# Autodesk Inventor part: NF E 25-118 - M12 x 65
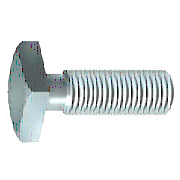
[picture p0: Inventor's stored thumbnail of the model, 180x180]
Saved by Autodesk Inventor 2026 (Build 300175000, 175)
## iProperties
Created: 2025-01
Part Number: NF E 25-118 - M12 x 65
Material: Acier, doux
Description: Vis à tête carrée. Produit de classe C. Symbole Q
Document SubType Name: Modeling
Standard: NF E 25-118
Designer: thierry.jost
Standards Organization: AFNOR
Language: fr-FR
Size Designation: M12 x 65
Categories: <MemberInstance><Categories><Category DisplayName="Visserie" InternalName="e4da775c-781d-43d5-af7c-5136215cf5a6" Mnemonic="FSTN"><Category DisplayName="Vis" Int
Density: 7.85 g/cm^3
Appearance: Semi-poli
IsCustomPart: 0
Author: thierry.jost
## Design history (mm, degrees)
revolve "Corps" stored, may be unused: angle "d5" = 90 deg
sketch "Esquisse2"
  geometry: L1 (-17.819, 0)-(17.819, 0) reference; L2 (0, -17.819)-(0, 17.819) reference; L3 (0, 12.728)-(12.728, 0); L4 (12.728, 0)-(0, -12.728); L5 (0, -12.728)-(-12.728, 0); L6 (-12.728, 0)-(0, 12.728); 1 further point
  constraints: 8 end point, 2 midpoint, 1 point on line, 7 other
  dimensions: "d6" = 18 distance between parallel lines of L3 L5 (= SW)
extrude "Tête" join sketch "Esquisse2" distance "d7" = 7.5 (= KOH); taper "d8" = 0 deg
revolve "Congé1" stored, may be unused: angle "d11" = 90 deg
workaxis "Work Axis1"
workplane "Work Plane1"
body "Solid1"
feature "Filetage" dims "d12" = 30 (= GEL), "d13" = 0
chamfer "Chanfrein1" distance "d14" = 0.94722 (= -0.5 x SPD + 0.5 x NND); stored, may be unused: second distance "d15" = 1.07364 (computed from GUL), angle "d19" = 45 deg
sketch "Esquisse1"
  geometry: L1 (-13, 0)-(78, 0) reference; L2 (0, -1.2)-(0, 7.2) reference; L3 (0, 0)-(65, 0); L4 (65, 0)-(65, 6); L5 (65, 6)-(35, 6); L6 (35, 6)-(33.926, 6); L7 (33.926, 6)-(0, 6); L8 (0, 6)-(0, 0)
  constraints: 12 end point, 3 parallel, 2 collinear, 2 perpendicular
  dimensions: "d0" = 12 diameter of L7 L3 (= BDM); "d1" = 12 diameter of L5 L3 (= NND); "d2" = 65 distance between parallel lines of L4 L8 (= NLG); "d3" = 30 distance from line of L5.end L4 (= GEL); "d4" = 1.07354 distance of L5.end L6.end (= GAL)
sketch "Esquisse3"
  geometry: L1 (0, -2.575)-(0, 15.448) reference; L2 (-9.433, 0)-(1.572, 0) reference; L3 (0, 12.728)-(-7.5, 12.728) reference; L4 (-7.5, 12.728)-(-7.5, 0) reference; A1 r 5.382 centre (-2.118, 9) between (-6, 12.728) and (-7.5, 9)
  constraints: 2 point on circle, 2 point on line, 1 centre point, 1 tangent
  dimensions: "d9" = 18 diameter of A1.end L2 (= SDH); "d10" = 1.5 distance from line of A1.start L4 (= 0.2 x KOH)
other parameters: "NLG" = 65 [user parameter; used in 1 equation term], "KOH" = 7.5 [user parameter; used in 2 equation terms], "NND" = 12 [user parameter; used in 4 equation terms], "GEL" = 30 [user parameter; used in 2 equation terms], "GAL" = 1.07354 (= 0.61345 x PTC) [user parameter; used in 1 equation term], "GUL" = 1.07354 (= 0.61345 x PTC) [user parameter; used in 1 equation term], "SW" = 18 [user parameter; used in 5 equation terms], "SPD" = 10.10557 (= NND - 1.08253 x PTC) [user parameter; used in 1 equation term], "BDM" = 12 (= NND) [user parameter; used in 1 equation term], "SDH" = 18 (= SW) [user parameter; used in 1 equation term], "d16" = 0, "d21" = 0, "d22" = 90 deg, "d23" = 0, "TPU" = 5.71429 (computed from PTC) [user parameter], "PDM" = 18 (= SW) [user parameter], "GD1" = 9.85293 (= THREADDIA - 1.2269 x PTC) [user parameter], "THREADDIA" = 12 [user parameter; used in 1 equation term], "TOA" = 30 deg [user parameter], "PTC" = 1.75 [user parameter; used in 5 equation terms], "PDME" = 18 (= SW) [user parameter], "E0" = 25.452 (= 1.414 x SW) [user parameter]
